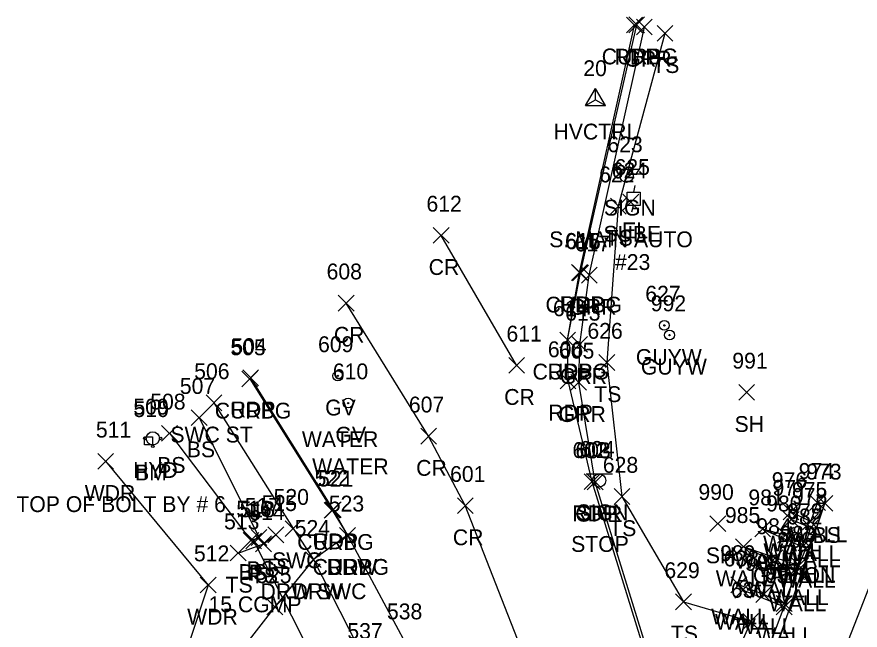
# Model space of a CAD drawing. Extents: x 1764889 to 1767296, y 695936 to 698960.
# Drawn here: x 1766247.4 to 1766353.9, y 696640.9 to 696718.4 of the extents above; entities that cross this region are included whole.
import ezdxf

# ---------------------------------------------------------------- set-up
doc = ezdxf.new("R2010")
doc.units = 0
for name, color, linetype in [('C_A', 7, 'Continuous'), ('C_C', 7, 'Continuous'), ('C_I', 7, 'Continuous'), ('CPBM', 7, 'Continuous'), ('CPSM', 7, 'Continuous'), ('D_A', 7, 'Continuous'), ('D_C', 7, 'Continuous'), ('D_I', 7, 'Continuous'), ('D_TIC', 7, 'Continuous'), ('DCP', 7, 'Continuous'), ('L_A', 7, 'Continuous'), ('L_C', 7, 'Continuous'), ('L_I', 7, 'Continuous'), ('L_TIC', 7, 'Continuous'), ('LAWA', 7, 'Continuous'), ('LELB', 7, 'Continuous'), ('LW', 7, 'Continuous'), ('P_A', 7, 'Continuous'), ('P_I', 7, 'Continuous'), ('P_TIC', 7, 'Continuous'), ('PET', 7, 'Continuous'), ('PRC', 7, 'Continuous'), ('R_A', 7, 'Continuous'), ('R_I', 7, 'Continuous'), ('R_TIC', 7, 'Continuous'), ('RC', 7, 'Continuous'), ('RDW', 7, 'Continuous'), ('RGR', 7, 'Continuous'), ('RSW', 7, 'Continuous'), ('S_A', 7, 'Continuous'), ('S_C', 7, 'Continuous'), ('S_I', 7, 'Continuous'), ('SSGN', 7, 'Continuous'), ('U_A', 7, 'Continuous'), ('U_C', 7, 'Continuous'), ('U_I', 7, 'Continuous'), ('U_TIC', 7, 'Continuous'), ('UEPT', 7, 'Continuous'), ('UPGW', 7, 'Continuous'), ('UWFH', 7, 'Continuous'), ('UWV', 7, 'Continuous')]:
    doc.layers.add(name, color=color, linetype=linetype)

msp = doc.modelspace()

# ---------------------------------------------------------------- linework, layer by layer
at = {"layer": 'CPBM'}
for p, q in [((1766263.53, 696664.35), (1766263.53, 696665.35)), ((1766263.53, 696665.35), (1766264.53, 696665.35)), ((1766264.03, 696664.85), (1766264.03, 696664.85)), ((1766264.03, 696664.85), (1766264.03, 696664.85)), ((1766264.53, 696665.35), (1766264.53, 696664.35)), ((1766264.53, 696664.35), (1766263.53, 696664.35))]:
    msp.add_line(p, q, dxfattribs=at)
at = {"layer": 'CPSM'}
for p, q in [((1766319.24, 696707.19), (1766320.49, 696709.35)), ((1766321.74, 696707.19), (1766320.49, 696709.35)), ((1766320.49, 696707.91), (1766320.49, 696709.35)), ((1766319.24, 696707.19), (1766320.49, 696707.91)), ((1766319.24, 696707.19), (1766321.74, 696707.19)), ((1766320.49, 696707.91), (1766320.49, 696707.91)), ((1766320.49, 696707.91), (1766321.74, 696707.19))]:
    msp.add_line(p, q, dxfattribs=at)
at = {"layer": 'D_TIC'}
for points in [[(1766276.33, 696651.19), (1766278.33, 696653.19)], [(1766278.33, 696651.19), (1766276.33, 696653.19)]]:
    msp.add_lwpolyline(points, dxfattribs=at)
at = {"layer": 'DCP'}
msp.add_lwpolyline([(1766277.33, 696652.19), (1766289.25, 696628.57)], dxfattribs=at)
at = {"layer": 'L_TIC'}
for points in [[(1766328.25, 696715.31), (1766330.25, 696717.31)], [(1766330.25, 696715.31), (1766328.25, 696717.31)], [(1766322.36, 696693.49), (1766324.36, 696695.49)], [(1766324.36, 696693.49), (1766322.36, 696695.49)], [(1766320.92, 696673.74), (1766322.92, 696675.74)], [(1766322.92, 696673.74), (1766320.92, 696675.74)], [(1766338.56, 696669.97), (1766340.56, 696671.97)], [(1766340.56, 696669.97), (1766338.56, 696671.97)], [(1766269.44, 696666.77), (1766271.44, 696668.77)], [(1766271.44, 696666.77), (1766269.44, 696668.77)], [(1766265.7, 696664.8), (1766267.7, 696666.8)], [(1766267.7, 696664.8), (1766265.7, 696666.8)], [(1766257.63, 696661.26), (1766259.63, 696663.26)], [(1766259.63, 696661.26), (1766257.63, 696663.26)], [(1766322.82, 696656.81), (1766324.82, 696658.81)], [(1766324.82, 696656.81), (1766322.82, 696658.81)], [(1766347.51, 696656.04), (1766349.51, 696658.04)], [(1766349.51, 696656.04), (1766347.51, 696658.04)], [(1766348.45, 696655.95), (1766350.45, 696657.95)], [(1766350.45, 696655.95), (1766348.45, 696657.95)], [(1766344.16, 696654.88), (1766346.16, 696656.88)], [(1766346.16, 696654.88), (1766344.16, 696656.88)], [(1766334.93, 696653.38), (1766336.93, 696655.38)], [(1766336.93, 696653.38), (1766334.93, 696655.38)], [(1766344.19, 696653.91), (1766346.19, 696655.91)], [(1766346.19, 696653.91), (1766344.19, 696655.91)], [(1766346.65, 696653.65), (1766348.65, 696655.65)], [(1766348.65, 696653.65), (1766346.65, 696655.65)], [(1766279.12, 696651.98), (1766281.12, 696653.98)], [(1766281.12, 696651.98), (1766279.12, 696653.98)], [(1766340.59, 696652.7), (1766342.59, 696654.7)], [(1766342.59, 696652.7), (1766340.59, 696654.7)], [(1766346.65, 696652.88), (1766348.65, 696654.88)], [(1766348.65, 696652.88), (1766346.65, 696654.88)], [(1766275.98, 696651.27), (1766277.98, 696653.27)], [(1766277.98, 696651.27), (1766275.98, 696653.27)], [(1766277, 696651.64), (1766279, 696653.64)], [(1766279, 696651.64), (1766277, 696653.64)], [(1766277, 696651.64), (1766279, 696653.64)], [(1766279, 696651.64), (1766277, 696653.64)], [(1766343.48, 696651.93), (1766345.48, 696653.93)], [(1766345.48, 696651.93), (1766343.48, 696653.93)], [(1766346.06, 696650.95), (1766348.06, 696652.95)], [(1766348.06, 696650.95), (1766346.06, 696652.95)], [(1766277.57, 696650.84), (1766279.57, 696652.84)], [(1766279.57, 696650.84), (1766277.57, 696652.84)], [(1766338.18, 696650.47), (1766340.18, 696652.47)], [(1766340.18, 696650.47), (1766338.18, 696652.47)], [(1766346.05, 696650.29), (1766348.05, 696652.29)], [(1766348.05, 696650.29), (1766346.05, 696652.29)], [(1766274.37, 696649.67), (1766276.37, 696651.67)], [(1766276.37, 696649.67), (1766274.37, 696651.67)], [(1766342.15, 696649.06), (1766344.15, 696651.06)], [(1766344.15, 696649.06), (1766342.15, 696651.06)], [(1766345.17, 696648.1), (1766347.17, 696650.1)], [(1766347.17, 696648.1), (1766345.17, 696650.1)], [(1766344.86, 696647.33), (1766346.86, 696649.33)], [(1766346.86, 696647.33), (1766344.86, 696649.33)], [(1766270.57, 696645.63), (1766272.57, 696647.63)], [(1766272.57, 696645.63), (1766270.57, 696647.63)], [(1766337.59, 696645.65), (1766339.59, 696647.65)], [(1766339.59, 696645.65), (1766337.59, 696647.65)], [(1766338.07, 696644.99), (1766340.07, 696646.99)], [(1766340.07, 696644.99), (1766338.07, 696646.99)], [(1766330.59, 696643.5), (1766332.59, 696645.5)], [(1766332.59, 696643.5), (1766330.59, 696645.5)], [(1766340.71, 696644.43), (1766342.71, 696646.43)], [(1766342.71, 696644.43), (1766340.71, 696646.43)], [(1766343.3, 696642.86), (1766345.3, 696644.86)], [(1766345.3, 696642.86), (1766343.3, 696644.86)], [(1766343.31, 696643.3), (1766345.31, 696645.3)], [(1766345.31, 696643.3), (1766343.31, 696645.3)], [(1766339.08, 696641.03), (1766341.08, 696643.03)], [(1766341.08, 696641.03), (1766339.08, 696643.03)]]:
    msp.add_lwpolyline(points, dxfattribs=at)
at = {"layer": 'LAWA'}
msp.add_lwpolyline([(1766258.63, 696662.26), (1766271.57, 696646.63), (1766267.22, 696633.39), (1766257.01, 696611.07)], dxfattribs=at)
at = {"layer": 'LELB'}
for points in [[(1766329.25, 696716.31), (1766323.36, 696694.49), (1766321.92, 696674.74), (1766323.82, 696657.81), (1766331.59, 696644.5), (1766340.08, 696642.03), (1766333.7, 696627.55)], [(1766270.44, 696667.77), (1766278, 696652.64)], [(1766266.7, 696665.8), (1766276.98, 696652.27), (1766278, 696652.64)], [(1766311.88, 696556.72), (1766333.81, 696592.11), (1766361.34, 696662.5)], [(1766341.89, 696634.51), (1766349.45, 696656.95)], [(1766275.37, 696650.67), (1766278.57, 696651.84), (1766280.12, 696652.98)]]:
    msp.add_lwpolyline(points, dxfattribs=at)
at = {"layer": 'LW'}
for points in [[(1766348.51, 696657.04), (1766347.65, 696654.65), (1766345.16, 696655.88)], [(1766345.19, 696654.91), (1766347.65, 696653.88), (1766347.06, 696651.95), (1766344.48, 696652.93), (1766341.59, 696653.7), (1766347.05, 696651.29), (1766346.17, 696649.1), (1766343.15, 696650.06), (1766339.18, 696651.47), (1766345.86, 696648.33), (1766344.31, 696644.3), (1766341.71, 696645.43), (1766338.59, 696646.65)], [(1766337.64, 696626.24), (1766344.3, 696643.86), (1766339.07, 696645.99)]]:
    msp.add_lwpolyline(points, dxfattribs=at)
at = {"layer": 'P_TIC'}
for points in [[(1766324.41, 696716.37), (1766326.41, 696718.37)], [(1766326.41, 696716.37), (1766324.41, 696718.37)], [(1766299.99, 696689.8), (1766301.99, 696691.8)], [(1766301.99, 696689.8), (1766299.99, 696691.8)], [(1766317.47, 696685.1), (1766319.47, 696687.1)], [(1766319.47, 696685.1), (1766317.47, 696687.1)], [(1766288.01, 696681.24), (1766290.01, 696683.24)], [(1766290.01, 696681.24), (1766288.01, 696683.24)], [(1766315.96, 696676.59), (1766317.96, 696678.59)], [(1766317.96, 696676.59), (1766315.96, 696678.59)], [(1766309.52, 696673.39), (1766311.52, 696675.39)], [(1766311.52, 696673.39), (1766309.52, 696675.39)], [(1766275.94, 696671.81), (1766277.94, 696673.81)], [(1766277.94, 696671.81), (1766275.94, 696673.81)], [(1766316.02, 696671.41), (1766318.02, 696673.41)], [(1766318.02, 696671.41), (1766316.02, 696673.41)], [(1766298.41, 696664.43), (1766300.41, 696666.43)], [(1766300.41, 696664.43), (1766298.41, 696666.43)], [(1766319.06, 696658.68), (1766321.06, 696660.68)], [(1766321.06, 696658.68), (1766319.06, 696660.68)], [(1766286.37, 696655.15), (1766288.37, 696657.15)], [(1766288.37, 696655.15), (1766286.37, 696657.15)], [(1766303.04, 696655.66), (1766305.04, 696657.66)], [(1766305.04, 696655.66), (1766303.04, 696657.66)], [(1766288.17, 696651.92), (1766290.17, 696653.92)], [(1766290.17, 696651.92), (1766288.17, 696653.92)]]:
    msp.add_lwpolyline(points, dxfattribs=at)
at = {"layer": 'PET'}
msp.add_lwpolyline([(1766276.94, 696672.81), (1766287.37, 696656.15), (1766289.17, 696652.92), (1766296.51, 696639.3), (1766298.45, 696635.69), (1766306.33, 696619.6), (1766316.81, 696595.84), (1766317.18, 696595.04), (1766319.04, 696590.19), (1766325.95, 696602.77), (1766333.45, 696616.59), (1766328.44, 696632.61), (1766320.06, 696659.68), (1766317.02, 696672.41), (1766316.96, 696677.59), (1766318.47, 696686.1), (1766325.41, 696717.37)], dxfattribs=at)
at = {"layer": 'PRC'}
for points in [[(1766310.52, 696674.39), (1766300.99, 696690.8)], [(1766325.95, 696602.77), (1766315.25, 696627.96), (1766304.04, 696656.66), (1766299.41, 696665.43), (1766289.01, 696682.24)]]:
    msp.add_lwpolyline(points, dxfattribs=at)
at = {"layer": 'R_TIC'}
for points in [[(1766324.69, 696716.4), (1766326.69, 696718.4)], [(1766326.69, 696716.4), (1766324.69, 696718.4)], [(1766325.65, 696716.11), (1766327.65, 696718.11)], [(1766327.65, 696716.11), (1766325.65, 696718.11)], [(1766317.59, 696685.05), (1766319.59, 696687.05)], [(1766319.59, 696685.05), (1766317.59, 696687.05)], [(1766318.7, 696684.78), (1766320.7, 696686.78)], [(1766320.7, 696684.78), (1766318.7, 696686.78)], [(1766315.96, 696676.59), (1766317.96, 696678.59)], [(1766317.96, 696676.59), (1766315.96, 696678.59)], [(1766317.49, 696676.03), (1766319.49, 696678.03)], [(1766319.49, 696676.03), (1766317.49, 696678.03)], [(1766275.82, 696671.66), (1766277.82, 696673.66)], [(1766277.82, 696671.66), (1766275.82, 696673.66)], [(1766317.36, 696671.23), (1766319.36, 696673.23)], [(1766319.36, 696671.23), (1766317.36, 696673.23)], [(1766271.31, 696668.64), (1766273.31, 696670.64)], [(1766273.31, 696668.64), (1766271.31, 696670.64)], [(1766319.44, 696658.64), (1766321.44, 696660.64)], [(1766321.44, 696658.64), (1766319.44, 696660.64)], [(1766286.24, 696655.07), (1766288.24, 696657.07)], [(1766288.24, 696655.07), (1766286.24, 696657.07)], [(1766281.29, 696652.76), (1766283.29, 696654.76)], [(1766283.29, 696652.76), (1766281.29, 696654.76)], [(1766288.17, 696651.92), (1766290.17, 696653.92)], [(1766290.17, 696651.92), (1766288.17, 696653.92)], [(1766288.17, 696651.92), (1766290.17, 696653.92)], [(1766290.17, 696651.92), (1766288.17, 696653.92)], [(1766283.86, 696648.84), (1766285.86, 696650.84)], [(1766285.86, 696648.84), (1766283.86, 696650.84)], [(1766283.86, 696648.84), (1766285.86, 696650.84)], [(1766285.86, 696648.84), (1766283.86, 696650.84)], [(1766279, 696642.88), (1766281, 696644.88)], [(1766281, 696642.88), (1766279, 696644.88)]]:
    msp.add_lwpolyline(points, dxfattribs=at)
at = {"layer": 'RC'}
for points in [[(1766316.96, 696677.59), (1766318.59, 696686.05), (1766325.69, 696717.4)], [(1766276.82, 696672.66), (1766287.24, 696656.07), (1766289.17, 696652.92)]]:
    msp.add_lwpolyline(points, dxfattribs=at)
at = {"layer": 'RDW'}
msp.add_lwpolyline([(1766289.17, 696652.92), (1766284.86, 696649.84), (1766280, 696643.88), (1766270.57, 696631.77), (1766260.05, 696607.82)], dxfattribs=at)
at = {"layer": 'RGR'}
msp.add_lwpolyline([(1766333.99, 696617.2), (1766328.78, 696632.67), (1766320.44, 696659.64), (1766318.36, 696672.23), (1766318.49, 696677.03), (1766319.7, 696685.78), (1766326.65, 696717.11)], dxfattribs=at)
at = {"layer": 'RSW'}
msp.add_lwpolyline([(1766272.31, 696669.64), (1766282.29, 696653.76), (1766284.86, 696649.84), (1766291.51, 696636.82), (1766293.45, 696633.25), (1766301.24, 696617.31), (1766311.74, 696594.41), (1766316.33, 696584.79), (1766318.33, 696589.37)], dxfattribs=at)
at = {"layer": 'SSGN'}
for p, q in [((1766322.76, 696699.16), (1766326.1, 696699.16)), ((1766324.41, 696698.32), (1766324.41, 696698.32)), ((1766319.31, 696660.67), (1766322.64, 696660.67)), ((1766320.95, 696659.84), (1766320.95, 696659.84))]:
    msp.add_line(p, q, dxfattribs=at)
for centre in [(1766324.41, 696698.32), (1766320.95, 696659.84)]:
    msp.add_circle(centre, 0.833, dxfattribs=at)
at = {"layer": 'U_TIC'}
for points in [[(1766323.95, 696694), (1766325.95, 696696)], [(1766325.95, 696694), (1766323.95, 696696)]]:
    msp.add_lwpolyline(points, dxfattribs=at)
at = {"layer": 'UEPT'}
for p, q in [((1766325.47, 696697.09), (1766325.3, 696696.26)), ((1766324.47, 696694.59), (1766324.47, 696696.26)), ((1766324.47, 696696.26), (1766326.14, 696696.26)), ((1766326.14, 696696.26), (1766326.14, 696694.59)), ((1766326.14, 696694.59), (1766324.47, 696694.59)), ((1766325.05, 696693.76), (1766325.3, 696694.59)), ((1766325.3, 696695.43), (1766325.3, 696695.43))]:
    msp.add_line(p, q, dxfattribs=at)
at = {"layer": 'UPGW'}
for centre, radius in [((1766329.18, 696679.43), 0.625), ((1766329.18, 696679.43), 0.0833), ((1766329.83, 696678.21), 0.625), ((1766329.83, 696678.21), 0.0833)]:
    msp.add_circle(centre, radius, dxfattribs=at)
at = {"layer": 'UWFH'}
msp.add_line((1766264.58, 696665.16), (1766264.58, 696665.16), dxfattribs=at)
for centre, radius in [((1766264.58, 696665.16), 0.833), ((1766263.58, 696665.16), 0.167), ((1766265.58, 696665.16), 0.167), ((1766264.58, 696664.16), 0.167)]:
    msp.add_circle(centre, radius, dxfattribs=at)
at = {"layer": 'UWV'}
for centre, radius in [((1766287.95, 696673.05), 0.625), ((1766287.95, 696673.05), 0.0833), ((1766289.25, 696669.62), 0.625), ((1766289.25, 696669.62), 0.0833)]:
    msp.add_circle(centre, radius, dxfattribs=at)

# ---------------------------------------------------------------- texts
at = {"layer": 'C_A'}
for s, p in [('HVCTRL', (1766315.18, 696702.91)), ('BM', (1766262.35, 696659.85))]:
    msp.add_text(s, height=2, dxfattribs=at).set_placement(p)
at = {"layer": 'C_C'}
msp.add_text('TOP OF BOLT BY # 6', height=2, dxfattribs=at).set_placement((1766247.36, 696655.85))
at = {"layer": 'C_I'}
for s, p in [('20', (1766318.94, 696710.91)), ('510', (1766262.15, 696667.85))]:
    msp.add_text(s, height=2, dxfattribs=at).set_placement(p)
at = {"layer": 'D_A'}
msp.add_text('P', height=2, dxfattribs=at).set_placement((1766276.71, 696647.19))
at = {"layer": 'D_C'}
msp.add_text('15 CGMP', height=2, dxfattribs=at).set_placement((1766271.62, 696643.19))
at = {"layer": 'D_I'}
msp.add_text('518', height=2, dxfattribs=at).set_placement((1766275.54, 696655.19))
at = {"layer": 'L_A'}
for s, p in [('TS', (1766327.65, 696711.31)), ('TS', (1766321.77, 696689.49)), ('TS', (1766320.33, 696669.74)), ('SH', (1766338.04, 696665.97)), ('BS', (1766268.88, 696662.77)), ('BS', (1766265.15, 696660.8)), ('WDR', (1766255.99, 696657.26)), ('TS', (1766322.22, 696652.81)), ('WALL', (1766344.99, 696652.04)), ('BS', (1766347.89, 696651.95)), ('WALL', (1766341.64, 696650.88)), ('WALL', (1766341.68, 696649.91)), ('SH', (1766334.42, 696649.38)), ('WALL', (1766344.14, 696649.65)), ('WALL', (1766344.14, 696648.88)), ('TS', (1766278.53, 696647.98)), ('WALL', (1766338.08, 696648.7)), ('WALL', (1766340.97, 696647.93)), ('BS', (1766275.42, 696647.27)), ('BS', (1766276.44, 696647.64)), ('BS', (1766276.44, 696647.64)), ('TS', (1766276.98, 696646.84)), ('WALL', (1766343.55, 696646.95)), ('TS', (1766273.78, 696645.67)), ('WALL', (1766335.67, 696646.47)), ('WALL', (1766343.54, 696646.29)), ('WALL', (1766339.64, 696645.06)), ('WALL', (1766342.66, 696644.1)), ('WALL', (1766342.35, 696643.33)), ('WDR', (1766268.93, 696641.63)), ('WALL', (1766335.08, 696641.65)), ('WALL', (1766335.56, 696640.99)), ('WALL', (1766338.2, 696640.43)), ('TS', (1766330, 696639.5)), ('WALL', (1766340.8, 696639.3))]:
    msp.add_text(s, height=2, dxfattribs=at).set_placement(p)
at = {"layer": 'L_C'}
msp.add_text('GABION', height=2, dxfattribs=at).set_placement((1766340.36, 696646.88))
at = {"layer": 'L_I'}
for s, p in [('622', (1766320.95, 696697.49)), ('626', (1766319.46, 696677.74)), ('991', (1766337.76, 696673.97)), ('507', (1766268, 696670.77)), ('508', (1766264.26, 696668.8)), ('511', (1766257.4, 696665.26)), ('628', (1766321.41, 696660.81)), ('974', (1766346.14, 696660.04)), ('973', (1766347.09, 696659.95)), ('976', (1766342.74, 696658.88)), ('990', (1766333.48, 696657.38)), ('977', (1766342.83, 696657.91)), ('975', (1766345.29, 696657.65)), ('981', (1766339.79, 696656.7)), ('978', (1766345.29, 696656.88)), ('516', (1766275.13, 696655.27)), ('517', (1766276.2, 696655.64)), ('517', (1766276.2, 696655.64)), ('515', (1766278.32, 696655.98)), ('980', (1766342.03, 696655.93)), ('514', (1766276.78, 696654.84)), ('985', (1766336.82, 696654.47)), ('979', (1766344.69, 696654.95)), ('982', (1766344.69, 696654.29)), ('513', (1766273.58, 696653.67)), ('984', (1766340.79, 696653.06)), ('983', (1766343.81, 696652.1)), ('986', (1766343.44, 696651.33)), ('512', (1766269.78, 696649.63)), ('989', (1766336.22, 696649.65)), ('638', (1766336.66, 696648.99)), ('988', (1766339.35, 696648.43)), ('629', (1766329.18, 696647.5)), ('637', (1766341.89, 696646.86)), ('987', (1766341.95, 696647.3)), ('630', (1766337.58, 696645.03))]:
    msp.add_text(s, height=2, dxfattribs=at).set_placement(p)
at = {"layer": 'P_A'}
for s, p in [('RDP', (1766322.89, 696712.37)), ('CR', (1766299.42, 696685.8)), ('RDP', (1766315.96, 696681.1)), ('CR', (1766287.45, 696677.24)), ('RDP', (1766314.45, 696672.59)), ('CR', (1766308.95, 696669.39)), ('RDP', (1766274.42, 696667.81)), ('RDP', (1766314.51, 696667.41)), ('CR', (1766297.84, 696660.43)), ('RDP', (1766317.55, 696654.68)), ('RDP', (1766284.86, 696651.15)), ('CR', (1766302.47, 696651.66)), ('RDP', (1766286.66, 696647.92))]:
    msp.add_text(s, height=2, dxfattribs=at).set_placement(p)
at = {"layer": 'P_I'}
for s, p in [('612', (1766299.14, 696693.8)), ('615', (1766316.63, 696689.1)), ('608', (1766286.53, 696685.24)), ('614', (1766315.11, 696680.59)), ('611', (1766309.24, 696677.39)), ('504', (1766274.5, 696675.81)), ('606', (1766314.47, 696675.41)), ('607', (1766296.92, 696668.43)), ('602', (1766317.57, 696662.68)), ('601', (1766302.12, 696659.66)), ('522', (1766285.01, 696659.15)), ('523', (1766286.81, 696655.92)), ('538', (1766294.15, 696642.3))]:
    msp.add_text(s, height=2, dxfattribs=at).set_placement(p)
at = {"layer": 'R_A'}
for s, p in [('CURBG', (1766321.27, 696712.4)), ('GRR', (1766324.14, 696712.11)), ('CURBG', (1766314.17, 696681.05)), ('GRR', (1766317.19, 696680.78)), ('CURBG', (1766312.54, 696672.59)), ('GRR', (1766315.98, 696672.03)), ('CURBG', (1766272.41, 696667.66)), ('GRR', (1766315.84, 696667.23)), ('SWC ST', (1766266.81, 696664.64)), ('GRR', (1766317.93, 696654.64)), ('CURBG', (1766282.82, 696651.07)), ('SWC', (1766279.65, 696648.76)), ('CURBG', (1766284.76, 696647.92)), ('DRW', (1766286.54, 696647.92)), ('DRW SWC', (1766278.19, 696644.84)), ('DRW', (1766282.23, 696644.84))]:
    msp.add_text(s, height=2, dxfattribs=at).set_placement(p)
at = {"layer": 'R_I'}
for s, p in [('616', (1766316.69, 696689.05)), ('617', (1766317.86, 696688.78)), ('614', (1766315.11, 696680.59)), ('613', (1766316.65, 696680.03)), ('505', (1766274.38, 696675.66)), ('605', (1766315.87, 696675.23)), ('506', (1766269.81, 696672.64)), ('603', (1766317.95, 696662.64)), ('521', (1766285.44, 696659.07)), ('520', (1766279.84, 696656.76)), ('523', (1766286.81, 696655.92)), ('523', (1766286.81, 696655.92)), ('524', (1766282.5, 696652.84)), ('524', (1766282.5, 696652.84)), ('525', (1766277.64, 696646.88)), ('538', (1766294.15, 696642.3)), ('538', (1766294.15, 696642.3)), ('537', (1766289.15, 696639.82)), ('537', (1766289.15, 696639.82))]:
    msp.add_text(s, height=2, dxfattribs=at).set_placement(p)
at = {"layer": 'S_A'}
for p in [(1766321.55, 696693.3), (1766318.09, 696654.82)]:
    msp.add_text('SIGN', height=2, dxfattribs=at).set_placement(p)
at = {"layer": 'S_C'}
for s, p in [('S. MAIN AUTO', (1766314.64, 696689.3)), ('STOP', (1766317.41, 696650.82))]:
    msp.add_text(s, height=2, dxfattribs=at).set_placement(p)
at = {"layer": 'S_I'}
for s, p in [('623', (1766321.98, 696701.3)), ('604', (1766318.44, 696662.82))]:
    msp.add_text(s, height=2, dxfattribs=at).set_placement(p)
at = {"layer": 'U_A'}
for s, p in [('EL', (1766323.84, 696690.43)), ('SUBE', (1766321.49, 696690)), ('GUYW', (1766325.58, 696674.43)), ('GUYW', (1766326.22, 696673.21)), ('GV', (1766286.35, 696668.05)), ('GV', (1766287.65, 696664.62)), ('HYD', (1766262.1, 696660.16))]:
    msp.add_text(s, height=2, dxfattribs=at).set_placement(p)
at = {"layer": 'U_C'}
for s, p in [('#23', (1766322.94, 696686.43)), ('WATER', (1766283.41, 696664.05)), ('WATER', (1766284.71, 696660.62))]:
    msp.add_text(s, height=2, dxfattribs=at).set_placement(p)
at = {"layer": 'U_I'}
for s, p in [('624', (1766322.54, 696698)), ('625', (1766322.89, 696698.43)), ('627', (1766326.77, 696682.43)), ('992', (1766327.46, 696681.21)), ('609', (1766285.45, 696676.05)), ('610', (1766287.32, 696672.62)), ('509', (1766262.13, 696668.16))]:
    msp.add_text(s, height=2, dxfattribs=at).set_placement(p)

doc.saveas('drawing.dxf')
